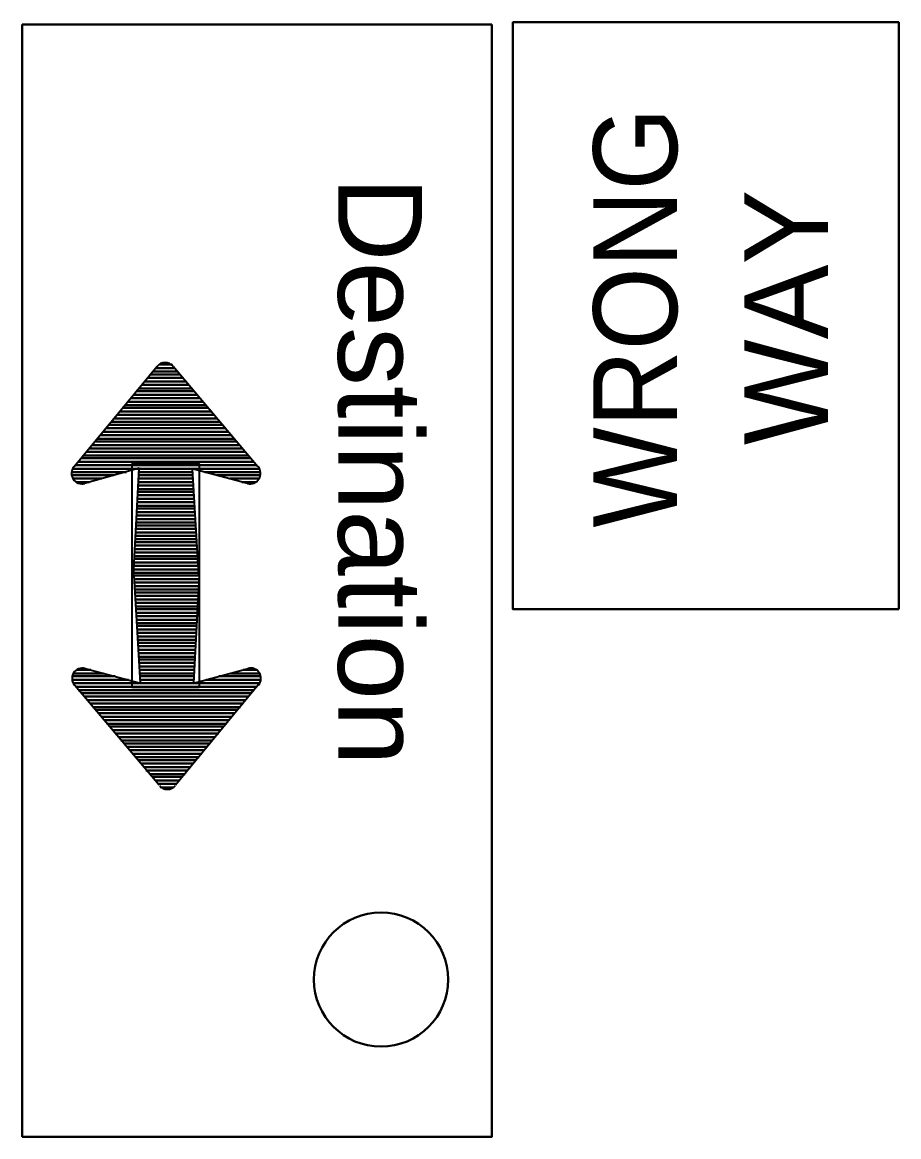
# Model space of a CAD drawing. Extents: x -198 to 658, y -402 to 142.
# Drawn here: x 258.86 to 288.96, y -204.29 to -166.01 of the extents above; entities that cross this region are included whole.
import ezdxf
from ezdxf.enums import TextEntityAlignment as Align

# ---------------------------------------------------------------- set-up
doc = ezdxf.new("R2010")
doc.units = 0
doc.header["$LTSCALE"] = 0.96
doc.layers.add('1', color=7, linetype='Continuous', lineweight=35)

msp = doc.modelspace()

# ---------------------------------------------------------------- linework, layer by layer
at = {"layer": '1', "lineweight": 40}
for p, q in [((274.989, -166.079), (258.861, -166.079)), ((258.861, -166.079), (258.861, -204.287)), ((264.093, -177.887), (263.445, -177.887)), ((263.829, -177.887), (263.445, -177.887)), ((264.501, -178.343), (263.061, -178.343)), ((263.829, -178.343), (263.061, -178.343)), ((264.381, -178.223), (263.157, -178.223)), ((263.829, -178.223), (263.157, -178.223)), ((264.285, -178.103), (263.253, -178.103)), ((263.829, -178.103), (263.253, -178.103)), ((264.189, -178.007), (263.349, -178.007)), ((263.829, -178.007), (263.349, -178.007)), ((264.765, -178.679), (262.773, -178.679)), ((263.829, -178.679), (262.773, -178.679)), ((264.669, -178.583), (262.869, -178.583)), ((263.829, -178.583), (262.869, -178.583)), ((264.573, -178.463), (262.965, -178.463)), ((263.829, -178.463), (262.965, -178.463)), ((265.053, -179.039), (262.509, -179.039)), ((263.829, -179.039), (262.509, -179.039)), ((264.957, -178.919), (262.581, -178.919)), ((263.829, -178.919), (262.581, -178.919)), ((264.861, -178.799), (262.677, -178.799)), ((263.829, -178.799), (262.677, -178.799)), ((265.437, -179.495), (262.125, -179.495)), ((263.829, -179.495), (262.125, -179.495)), ((265.365, -179.375), (262.221, -179.375)), ((263.829, -179.375), (262.221, -179.375)), ((265.245, -179.255), (262.293, -179.255)), ((263.829, -179.255), (262.293, -179.255)), ((265.149, -179.159), (262.389, -179.159)), ((263.829, -179.159), (262.389, -179.159)), ((265.749, -179.831), (261.837, -179.831)), ((263.829, -179.831), (261.837, -179.831)), ((265.653, -179.735), (261.933, -179.735)), ((263.829, -179.735), (261.933, -179.735)), ((265.557, -179.615), (262.005, -179.615)), ((263.829, -179.615), (262.005, -179.615)), ((266.037, -180.191), (261.549, -180.191)), ((263.829, -180.191), (261.549, -180.191)), ((265.941, -180.071), (261.645, -180.071)), ((263.829, -180.071), (261.645, -180.071)), ((265.845, -179.951), (261.741, -179.951)), ((263.829, -179.951), (261.741, -179.951)), ((266.421, -180.647), (261.165, -180.647)), ((263.829, -180.647), (261.165, -180.647)), ((266.325, -180.527), (261.261, -180.527)), ((263.829, -180.527), (261.261, -180.527)), ((266.229, -180.407), (261.357, -180.407)), ((263.829, -180.407), (261.357, -180.407)), ((266.133, -180.311), (261.453, -180.311)), ((263.829, -180.311), (261.453, -180.311)), ((266.709, -180.983), (260.877, -180.983)), ((263.829, -180.983), (260.877, -180.983)), ((266.613, -180.887), (260.973, -180.887)), ((263.829, -180.887), (260.973, -180.887)), ((266.517, -180.767), (261.069, -180.767)), ((263.829, -180.767), (261.069, -180.767)), ((266.901, -181.223), (260.685, -181.223)), ((263.829, -181.223), (260.685, -181.223)), ((266.829, -181.103), (260.781, -181.103)), ((263.829, -181.103), (260.781, -181.103)), ((263.829, -181.343), (262.869, -181.343)), ((262.437, -181.463), (260.565, -181.463)), ((262.437, -181.463), (260.565, -181.463)), ((262.005, -181.559), (260.565, -181.559)), ((262.005, -181.559), (260.565, -181.559)), ((264.717, -181.799), (262.845, -181.799)), ((263.829, -181.799), (262.845, -181.799)), ((264.693, -181.463), (262.869, -181.463)), ((263.829, -181.463), (262.869, -181.463)), ((264.717, -181.559), (262.869, -181.559)), ((263.829, -181.559), (262.869, -181.559)), ((264.717, -181.679), (262.869, -181.679)), ((263.829, -181.679), (262.869, -181.679)), ((267.045, -181.463), (265.125, -181.463)), ((266.997, -181.679), (265.989, -181.679)), ((264.741, -181.919), (262.845, -181.919)), ((263.829, -181.919), (262.845, -181.919)), ((264.741, -182.039), (262.845, -182.039)), ((263.829, -182.039), (262.845, -182.039)), ((264.741, -182.135), (262.845, -182.135)), ((263.829, -182.135), (262.845, -182.135)), ((264.741, -182.255), (262.821, -182.255)), ((263.829, -182.255), (262.821, -182.255)), ((264.765, -182.375), (262.821, -182.375)), ((263.829, -182.375), (262.821, -182.375)), ((264.765, -182.495), (262.821, -182.495)), ((263.829, -182.495), (262.821, -182.495)), ((264.789, -182.951), (262.797, -182.951)), ((263.829, -182.951), (262.797, -182.951)), ((264.765, -182.615), (262.821, -182.615)), ((263.829, -182.615), (262.821, -182.615)), ((264.765, -182.711), (262.821, -182.711)), ((263.829, -182.711), (262.821, -182.711)), ((264.789, -182.831), (262.821, -182.831)), ((263.829, -182.831), (262.821, -182.831)), ((264.813, -183.287), (262.773, -183.287)), ((263.829, -183.287), (262.773, -183.287)), ((264.789, -183.071), (262.797, -183.071)), ((263.829, -183.071), (262.797, -183.071)), ((264.813, -183.191), (262.797, -183.191)), ((263.829, -183.191), (262.797, -183.191)), ((264.813, -183.407), (262.773, -183.407)), ((263.829, -183.407), (262.773, -183.407)), ((264.813, -183.527), (262.773, -183.527)), ((263.829, -183.527), (262.773, -183.527)), ((264.837, -183.647), (262.773, -183.647)), ((263.829, -183.647), (262.773, -183.647)), ((264.837, -183.767), (262.749, -183.767)), ((263.829, -183.767), (262.749, -183.767)), ((264.837, -183.863), (262.749, -183.863)), ((263.829, -183.863), (262.749, -183.863)), ((264.837, -183.983), (262.749, -183.983)), ((263.829, -183.983), (262.749, -183.983)), ((264.861, -184.103), (262.749, -184.103)), ((263.829, -184.103), (262.749, -184.103)), ((264.861, -184.223), (262.725, -184.223)), ((263.829, -184.223), (262.725, -184.223)), ((264.861, -184.343), (262.725, -184.343)), ((263.829, -184.343), (262.725, -184.343)), ((264.861, -184.439), (262.725, -184.439)), ((263.829, -184.439), (262.725, -184.439)), ((264.885, -184.679), (262.701, -184.679)), ((263.829, -184.679), (262.701, -184.679)), ((264.885, -184.799), (262.701, -184.799)), ((263.829, -184.799), (262.701, -184.799)), ((264.885, -184.559), (262.725, -184.559)), ((263.829, -184.559), (262.725, -184.559)), ((264.909, -185.015), (262.677, -185.015)), ((263.829, -185.015), (262.677, -185.015)), ((264.909, -184.919), (262.701, -184.919)), ((263.829, -184.919), (262.701, -184.919)), ((262.701, -185.015), (264.933, -185.015)), ((262.701, -185.135), (264.909, -185.135)), ((262.725, -185.255), (264.909, -185.255)), ((263.781, -185.015), (264.933, -185.015)), ((263.781, -185.135), (264.909, -185.135)), ((263.781, -185.255), (264.909, -185.255)), ((262.725, -185.375), (264.909, -185.375)), ((262.725, -185.495), (264.885, -185.495)), ((262.749, -185.591), (264.885, -185.591)), ((263.781, -185.375), (264.909, -185.375)), ((263.781, -185.495), (264.885, -185.495)), ((263.781, -185.591), (264.885, -185.591)), ((262.749, -185.711), (264.885, -185.711)), ((262.749, -185.831), (264.885, -185.831)), ((262.749, -185.951), (264.861, -185.951)), ((263.781, -185.711), (264.885, -185.711)), ((263.781, -185.831), (264.885, -185.831)), ((263.781, -185.951), (264.861, -185.951)), ((262.773, -186.071), (264.861, -186.071)), ((262.773, -186.167), (264.861, -186.167)), ((262.773, -186.287), (264.861, -186.287)), ((262.797, -186.407), (264.837, -186.407)), ((263.781, -186.071), (264.861, -186.071)), ((263.781, -186.167), (264.861, -186.167)), ((263.781, -186.287), (264.861, -186.287)), ((263.781, -186.407), (264.837, -186.407)), ((262.797, -186.527), (264.837, -186.527)), ((262.797, -186.647), (264.837, -186.647)), ((262.797, -186.743), (264.837, -186.743)), ((263.781, -186.527), (264.837, -186.527)), ((263.781, -186.647), (264.837, -186.647)), ((263.781, -186.743), (264.837, -186.743)), ((262.797, -186.863), (264.813, -186.863)), ((262.821, -186.983), (264.813, -186.983)), ((262.821, -187.103), (264.813, -187.103)), ((263.781, -186.863), (264.813, -186.863)), ((263.781, -186.983), (264.813, -186.983)), ((263.781, -187.103), (264.813, -187.103)), ((262.821, -187.223), (264.813, -187.223)), ((262.845, -187.319), (264.813, -187.319)), ((262.845, -187.439), (264.789, -187.439)), ((262.845, -187.559), (264.789, -187.559)), ((263.781, -187.223), (264.813, -187.223)), ((263.781, -187.319), (264.813, -187.319)), ((263.781, -187.439), (264.789, -187.439)), ((263.781, -187.559), (264.789, -187.559)), ((262.845, -187.679), (264.789, -187.679)), ((262.869, -187.799), (264.789, -187.799)), ((262.869, -187.895), (264.765, -187.895)), ((263.781, -187.679), (264.789, -187.679)), ((263.781, -187.799), (264.789, -187.799)), ((263.781, -187.895), (264.765, -187.895)), ((262.869, -188.015), (264.765, -188.015)), ((262.869, -188.135), (264.765, -188.135)), ((262.893, -188.255), (264.765, -188.255)), ((263.781, -188.015), (264.765, -188.015)), ((263.781, -188.135), (264.765, -188.135)), ((263.781, -188.255), (264.765, -188.255)), ((260.565, -188.591), (262.509, -188.591)), ((260.613, -188.375), (261.645, -188.375)), ((262.893, -188.375), (264.741, -188.375)), ((262.893, -188.471), (264.741, -188.471)), ((262.917, -188.591), (264.741, -188.591)), ((263.781, -188.375), (264.741, -188.375)), ((263.781, -188.471), (264.741, -188.471)), ((263.781, -188.591), (264.741, -188.591)), ((263.781, -188.711), (264.741, -188.711)), ((265.173, -188.591), (267.045, -188.591)), ((265.173, -188.591), (267.045, -188.591)), ((265.605, -188.471), (267.045, -188.471)), ((265.605, -188.471), (267.045, -188.471)), ((260.709, -188.831), (266.925, -188.831)), ((260.781, -188.951), (266.829, -188.951)), ((260.901, -189.047), (266.733, -189.047)), ((263.781, -188.831), (266.925, -188.831)), ((263.781, -188.951), (266.829, -188.951)), ((263.781, -189.047), (266.733, -189.047)), ((260.997, -189.167), (266.637, -189.167)), ((261.093, -189.287), (266.541, -189.287)), ((261.189, -189.407), (266.445, -189.407)), ((263.781, -189.167), (266.637, -189.167)), ((263.781, -189.287), (266.541, -189.287)), ((263.781, -189.407), (266.445, -189.407)), ((261.285, -189.527), (266.349, -189.527)), ((261.381, -189.623), (266.253, -189.623)), ((261.477, -189.743), (266.157, -189.743)), ((261.573, -189.863), (266.061, -189.863)), ((263.781, -189.527), (266.349, -189.527)), ((263.781, -189.623), (266.253, -189.623)), ((263.781, -189.743), (266.157, -189.743)), ((263.781, -189.863), (266.061, -189.863)), ((261.669, -189.983), (265.965, -189.983)), ((261.765, -190.103), (265.869, -190.103)), ((261.861, -190.199), (265.773, -190.199)), ((263.781, -189.983), (265.965, -189.983)), ((263.781, -190.103), (265.869, -190.103)), ((263.781, -190.199), (265.773, -190.199)), ((261.957, -190.319), (265.677, -190.319)), ((262.053, -190.439), (265.605, -190.439)), ((262.173, -190.559), (265.485, -190.559)), ((263.781, -190.319), (265.677, -190.319)), ((263.781, -190.439), (265.605, -190.439)), ((263.781, -190.559), (265.485, -190.559)), ((262.245, -190.679), (265.389, -190.679)), ((262.365, -190.775), (265.317, -190.775)), ((262.461, -190.895), (265.221, -190.895)), ((262.557, -191.015), (265.101, -191.015)), ((263.781, -190.679), (265.389, -190.679)), ((263.781, -190.775), (265.317, -190.775)), ((263.781, -190.895), (265.221, -190.895)), ((263.781, -191.015), (265.101, -191.015)), ((262.653, -191.135), (265.029, -191.135)), ((262.749, -191.255), (264.933, -191.255)), ((262.845, -191.351), (264.837, -191.351)), ((263.781, -191.135), (265.029, -191.135)), ((263.781, -191.255), (264.933, -191.255)), ((263.781, -191.351), (264.837, -191.351)), ((262.941, -191.471), (264.741, -191.471)), ((263.037, -191.591), (264.645, -191.591)), ((263.109, -191.711), (264.549, -191.711)), ((263.781, -191.471), (264.741, -191.471)), ((263.781, -191.591), (264.645, -191.591)), ((263.781, -191.711), (264.549, -191.711)), ((263.229, -191.831), (264.453, -191.831)), ((263.325, -191.927), (264.357, -191.927)), ((263.421, -192.047), (264.261, -192.047)), ((263.781, -191.831), (264.453, -191.831)), ((263.781, -191.927), (264.357, -191.927)), ((263.781, -192.047), (264.261, -192.047)), ((263.517, -192.167), (264.165, -192.167)), ((263.781, -192.167), (264.165, -192.167))]:
    msp.add_line(p, q, dxfattribs=at)
at = {"layer": '1'}
for p, q in [((260.637, -181.271), (263.493, -177.815)), ((264.045, -177.815), (266.949, -181.271)), ((263.565, -192.215), (260.661, -188.783)), ((266.973, -188.759), (264.117, -192.215))]:
    msp.add_line(p, q, dxfattribs=at)
at = {"layer": '1', "lineweight": 40}
for points in [[(274.989, -166.079), (274.989, -204.287), (258.861, -204.287)], [(263.829, -177.767), (263.565, -177.767), (263.565, -177.767)], [(263.973, -177.767), (263.997, -177.767), (263.973, -177.767), (263.565, -177.767), (263.565, -177.767)], [(262.845, -181.343), (260.613, -181.343), (260.589, -181.343)], [(262.845, -181.343), (260.613, -181.343), (260.589, -181.343)], [(266.997, -181.343), (266.997, -181.343), (264.693, -181.343), (262.869, -181.343)], [(261.597, -181.679), (260.613, -181.679), (260.589, -181.679)], [(261.597, -181.679), (260.613, -181.679), (260.589, -181.679)], [(261.165, -181.799), (260.709, -181.799), (260.709, -181.799)], [(261.165, -181.799), (260.709, -181.799), (260.709, -181.799)], [(267.045, -181.559), (267.021, -181.559), (265.557, -181.559)], [(266.877, -181.799), (266.877, -181.799), (266.397, -181.799)], [(260.733, -188.255), (260.733, -188.255), (261.213, -188.255)], [(266.445, -188.255), (266.901, -188.255), (266.901, -188.255)], [(266.445, -188.255), (266.901, -188.255), (266.901, -188.255)], [(260.565, -188.471), (260.589, -188.471), (262.053, -188.471)], [(260.613, -188.711), (260.613, -188.711), (262.917, -188.711), (264.741, -188.711)], [(264.765, -188.711), (266.997, -188.711), (267.021, -188.711)], [(264.765, -188.711), (266.997, -188.711), (267.021, -188.711)], [(266.013, -188.375), (266.997, -188.375), (267.021, -188.375)], [(266.013, -188.375), (266.997, -188.375), (267.021, -188.375)], [(263.637, -192.287), (263.613, -192.287), (263.637, -192.287), (264.045, -192.287), (264.045, -192.287)], [(263.781, -192.287), (264.045, -192.287), (264.045, -192.287)]]:
    msp.add_lwpolyline(points, dxfattribs=at)
msp.add_lwpolyline([(288.957, -186.167), (288.957, -166.007), (275.709, -166.007), (275.709, -186.167)], close=True, dxfattribs=at)
at = {"layer": '1'}
for points in [[(266.589, -181.847), (264.693, -181.343), (264.909, -185.015), (262.677, -185.015), (262.869, -181.319), (260.997, -181.847)], [(261.021, -188.207), (262.917, -188.711), (262.701, -185.015), (264.933, -185.015), (264.741, -188.711), (266.613, -188.207)]]:
    msp.add_lwpolyline(points, dxfattribs=at)
msp.add_lwpolyline([(264.933, -188.855), (262.629, -188.855), (262.629, -181.175), (264.933, -181.175)], close=True, dxfattribs=at)
at = {"layer": '1', "lineweight": 40}
msp.add_circle((271.1801, -198.8883), 2.304, dxfattribs=at)
at = {"layer": '1'}
for centre, start, end in [((263.7655, -178.0538), 40.25653, 140.40471), ((260.9095, -181.5049), 140.43005, 285.55122), ((266.6855, -181.5007), 255.11373, 40.25762), ((260.925, -188.5493), 75.11373, 220.25762), ((266.7011, -188.5451), 320.43005, 105.55122), ((263.845, -191.9963), 220.25653, 320.40471)]:
    msp.add_arc(centre, 0.3571, start, end, dxfattribs=at)

# ---------------------------------------------------------------- texts
for s, rotation, width, p in [('WRONG', 90, 0.95, (281.349, -176.1516)), ('Destination', 270, 1.05, (269.709, -181.4203))]:
    msp.add_text(s, height=2.88, rotation=rotation, dxfattribs=dict(at, width=width)).set_placement(p, align=Align.CENTER)
msp.add_text('WAY', height=2.88, rotation=90, dxfattribs=at).set_placement((286.533, -176.145), align=Align.CENTER)

doc.saveas('drawing.dxf')
